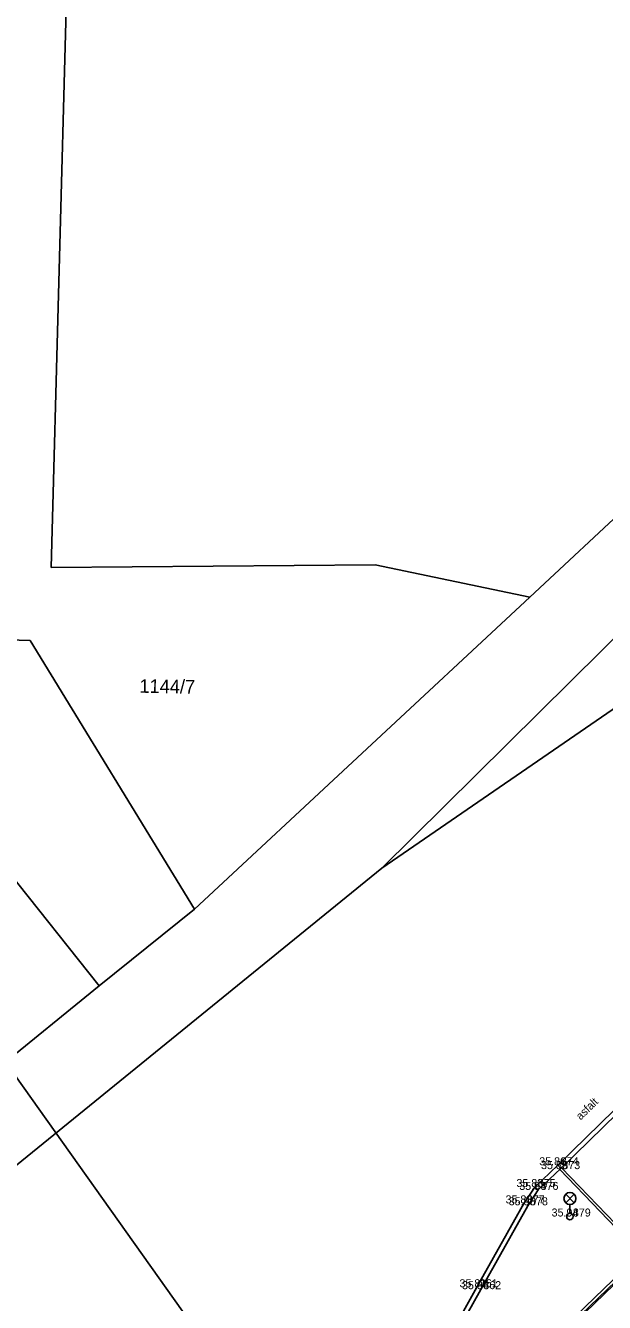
# Model space of a CAD drawing. Extents: x -609709 to -609357, y -1051535 to -1051131.
# Drawn here: x -609637.29 to -609619.19, y -1051267.96 to -1051228.08 of the extents above; entities that cross this region are included whole.
import ezdxf

# ---------------------------------------------------------------- set-up
doc = ezdxf.new("R2010")
doc.units = 0
for name, color, linetype in [('Vrstva 1', 7, 'Continuous'), ('Vrstva 10', 7, 'Continuous'), ('Vrstva 12', 7, 'Continuous'), ('Vrstva 2', 7, 'Continuous'), ('Vrstva 3', 7, 'Continuous'), ('Vrstva 4', 7, 'Continuous'), ('Vrstva 5', 7, 'Continuous')]:
    doc.layers.add(name, color=color, linetype=linetype)

msp = doc.modelspace()

# ---------------------------------------------------------------- linework, layer by layer
at = {"layer": 'Vrstva 1'}
for p, q in [((-609620.65, -1051263.68), (-609620.65, -1051263.68)), ((-609620.6, -1051263.8), (-609620.6, -1051263.8)), ((-609621.37, -1051264.36), (-609621.37, -1051264.36)), ((-609621.28, -1051264.45), (-609621.28, -1051264.45)), ((-609621.71, -1051264.87), (-609621.71, -1051264.87)), ((-609621.61, -1051264.93), (-609621.61, -1051264.93)), ((-609620.27, -1051265.28), (-609620.27, -1051265.28)), ((-609623.18, -1051267.49), (-609623.18, -1051267.49)), ((-609623.07, -1051267.55), (-609623.07, -1051267.55))]:
    msp.add_line(p, q, dxfattribs=at)
at = {"layer": 'Vrstva 10'}
for p, q in [((-609636.49, -1051245.01), (-609635.11, -1051193.94)), ((-609621.52, -1051245.94), (-609611.96, -1051237)), ((-609626.15, -1051254.4), (-609612.01, -1051240.42)), ((-609623.53, -1051271.88), (-609592.58, -1051242.01)), ((-609636.49, -1051245.01), (-609626.36, -1051244.93)), ((-609626.36, -1051244.93), (-609621.52, -1051245.94)), ((-609632.01, -1051255.68), (-609621.52, -1051245.94)), ((-609654.02, -1051246.74), (-609637.14, -1051247.29)), ((-609626.15, -1051254.4), (-609615.29, -1051246.93)), ((-609637.14, -1051247.29), (-609632.01, -1051255.68)), ((-609640.9, -1051266.38), (-609626.15, -1051254.4)), ((-609637.85, -1051254.47), (-609634.99, -1051258.08)), ((-609634.99, -1051258.08), (-609632.01, -1051255.68)), ((-609640.34, -1051262.42), (-609634.99, -1051258.08))]:
    msp.add_line(p, q, dxfattribs=at)
at = {"layer": 'Vrstva 12'}
msp.add_lwpolyline([(-609644.336, -1051251.436), (-609604.801, -1051307.048), (-609620.698, -1051318.606), (-609619.426, -1051320.272)], dxfattribs=at)
at = {"layer": 'Vrstva 4'}
for q in [(-609620.529, -1051263.758), (-609621.175, -1051269.548)]:
    msp.add_line((-609617.947, -1051266.442), q, dxfattribs=at)
for points in [[(-609602.18, -1051251.07), (-609605.07, -1051253.83), (-609609.18, -1051257.81), (-609614.3, -1051258.05), (-609615.05, -1051258.25), (-609617.76, -1051260.87), (-609618.44, -1051261.52), (-609620.65, -1051263.68), (-609621.37, -1051264.36), (-609621.71, -1051264.87), (-609623.18, -1051267.49), (-609624.27, -1051269.45), (-609624.77, -1051270.32), (-609626.73, -1051273.81), (-609627.2, -1051274.7), (-609627.81, -1051275.78), (-609632.5, -1051279.47)], [(-609602.083, -1051251.171), (-609604.973, -1051253.931), (-609609.121, -1051257.947), (-609614.278, -1051258.189), (-609614.979, -1051258.376), (-609617.663, -1051260.971), (-609618.343, -1051261.621), (-609620.553, -1051263.781), (-609621.262, -1051264.451), (-609621.591, -1051264.943), (-609623.058, -1051267.558), (-609624.148, -1051269.519), (-609624.648, -1051270.389), (-609626.607, -1051273.877), (-609627.077, -1051274.767), (-609627.702, -1051275.873), (-609632.413, -1051279.58)], [(-609620.65, -1051263.68), (-609620.553, -1051263.781)], [(-609618.06, -1051266.44), (-609620.587, -1051263.813)], [(-609621.37, -1051264.36), (-609621.262, -1051264.451)], [(-609618.06, -1051266.44), (-609621.23, -1051269.49)]]:
    msp.add_lwpolyline(points, dxfattribs=at)
at = {"layer": 'Vrstva 5'}
for p, q in [((-609620.402, -1051264.85), (-609620.138, -1051264.585)), ((-609620.402, -1051264.585), (-609620.138, -1051264.85)), ((-609620.27, -1051264.905), (-609620.27, -1051265.18))]:
    msp.add_line(p, q, dxfattribs=at)
for centre, radius in [((-609620.27, -1051264.718), 0.188), ((-609620.27, -1051265.28), 0.1)]:
    msp.add_circle(centre, radius, dxfattribs=at)

# ---------------------------------------------------------------- texts
at = {"layer": 'Vrstva 10'}
msp.add_text('1144/7', height=0.425, rotation=359.0582, dxfattribs=at).set_placement((-609633.73, -1051248.92))
at = {"layer": 'Vrstva 2'}
for s, p in [(' 874', (-609620.65, -1051263.68)), (' 873', (-609620.6, -1051263.8)), (' 875', (-609621.37, -1051264.36)), (' 876', (-609621.28, -1051264.45)), (' 877', (-609621.71, -1051264.87)), (' 878', (-609621.61, -1051264.93)), (' 879', (-609620.27, -1051265.28)), (' 861', (-609623.18, -1051267.49)), (' 862', (-609623.07, -1051267.55))]:
    msp.add_text(s, height=0.25, dxfattribs=at).set_placement(p)
at = {"layer": 'Vrstva 3'}
for s, p in [('35.86', (-609621.229, -1051263.68)), ('35.89', (-609621.173, -1051263.8)), ('35.83', (-609621.943, -1051264.36)), ('35.94', (-609621.853, -1051264.45)), ('35.83', (-609622.283, -1051264.87)), ('35.95', (-609622.183, -1051264.93)), ('35.94', (-609620.843, -1051265.28)), ('35.81', (-609623.722, -1051267.49)), ('35.94', (-609623.643, -1051267.55))]:
    msp.add_text(s, height=0.25, dxfattribs=at).set_placement(p)
at = {"layer": 'Vrstva 4'}
msp.add_text('asfalt', height=0.25, rotation=44.3445, dxfattribs=at).set_placement((-609619.937, -1051262.284))

doc.saveas('drawing.dxf')
